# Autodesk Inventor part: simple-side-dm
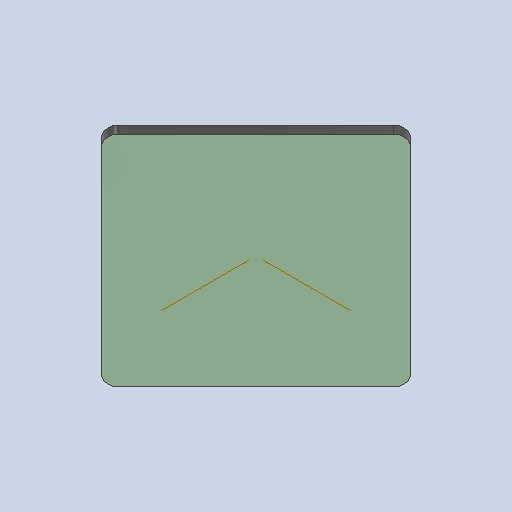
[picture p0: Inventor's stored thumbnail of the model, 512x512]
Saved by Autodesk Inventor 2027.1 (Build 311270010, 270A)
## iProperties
Created: 2026-07
Part Number: simple-side-dm
Material: Generic
Document SubType Name: Modeling
Designer: dunge
Density: 1 g/cm^3
Appearance: Default
Author: dunge
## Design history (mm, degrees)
sketch "Sketch1"
  geometry: L1 (0.508, -0.508)-(-0.508, 0.508); L2 (-0.508, 0.508)-(-10.668, -9.652); L3 (-10.668, -9.652)-(-9.652, -10.668); L4 (-9.652, -10.668)-(0.508, -0.508); L5 (0, 0)-(0.419, 0)
  constraints: 10 end point, 3 perpendicular, 2 midpoint, 1 horizontal
  dimensions: "d0" = 45 deg angle of L1 L5; "d1" = 1.016 horizontal distance of L1.start L1.end; "d2" = 10.16 horizontal distance of L3.end L1.start
revolve "Revolution1" sketch "Sketch1" stored, may be unused: angle "d3" = 90 deg
workpoint "Work Point1"
  workaxis "Work Axis3"
  workaxis "Work Axis4"
sketch "Sketch2"
  geometry: L1 (-14.368, -14.368)-(14.368, -14.368); L2 (14.368, -14.368)-(14.368, 14.368); L3 (14.368, 14.368)-(-14.368, 14.368); L4 (-14.368, 14.368)-(-14.368, -14.368); L5 (-14.368, -14.368)-(14.368, 14.368); L6 (14.368, -14.368)-(-14.368, 14.368); C1 r 14.368 at (0, 0) reference; 5 further points
  constraints: 12 end point, 2 midpoint, 2 parallel, 2 tangent, 1 horizontal, 1 perpendicular
extrude "Extrusion1" join sketch "Sketch2" stored distance "d4" = 25.4; taper "d5" = 0 deg
fillet "Fillet1" dims "d6" = 1.5875
body "Solid1"
node "Finishes"
node "Finish1" dims "Finish1_Area" = 164.7283
node "Finish2" dims "Finish2_Area" = 16.12449
